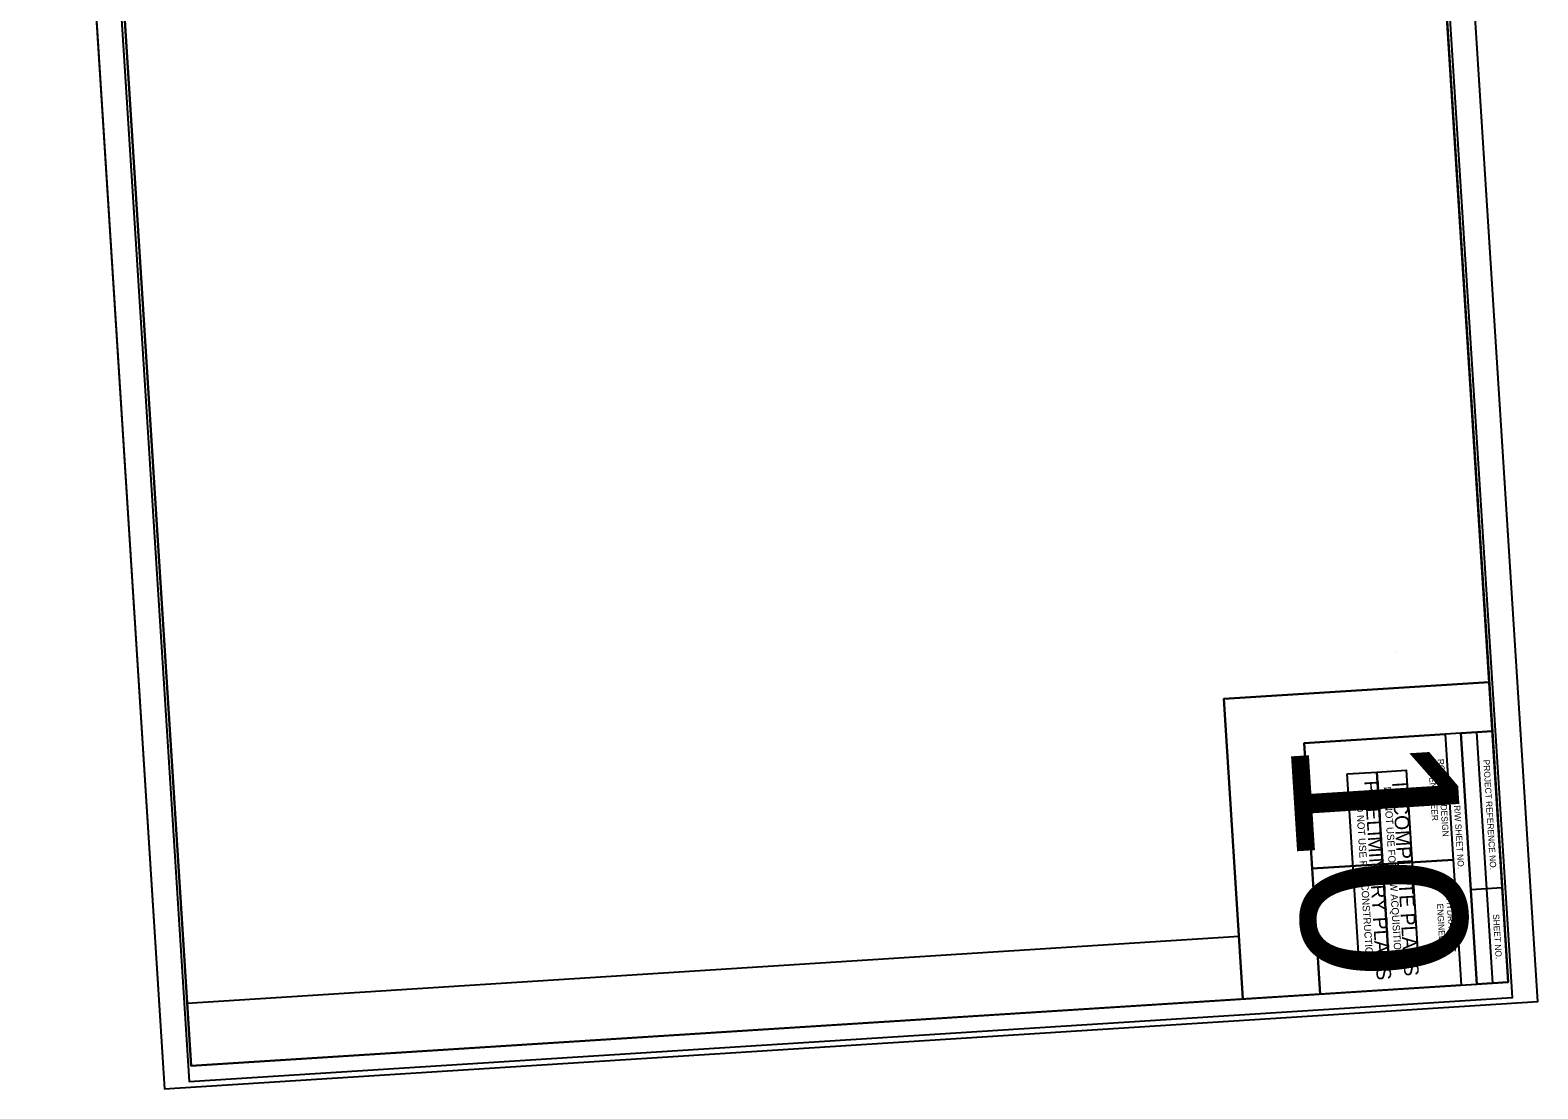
# Model space of a CAD drawing. Extents: x 1778994 to 1784559, y 810461 to 816654.
# Drawn here: x 1780418 to 1781618, y 810461 to 811304 of the extents above; entities that cross this region are included whole.
import ezdxf

# ---------------------------------------------------------------- set-up
doc = ezdxf.new("R2010")
doc.units = 0
for name, color, linetype in [('Sheet Clip Boundary CELL', 7, 'Continuous'), ('Sheet Cutting Line CELL', 7, 'Continuous'), ('Sheet Layout Plan Border', 7, 'Continuous'), ('Sheet North Arrow Point CELL', 7, 'Continuous'), ('Sheet Plan CELL', 7, 'Continuous'), ('Sheet Plan Layout CELL', 7, 'Continuous'), ('Sheet Plot Border Inside CELL', 7, 'Continuous'), ('Sheet Plot Border Outside CELL', 7, 'Continuous'), ('Sheet Sticker Incomplete CELL', 7, 'Continuous'), ('Sheet Sticker Preliminary CELL', 7, 'Continuous')]:
    doc.layers.add(name, color=color, linetype=linetype)

msp = doc.modelspace()

# ---------------------------------------------------------------- linework, layer by layer
at = {"layer": 'Sheet Clip Boundary CELL'}
msp.add_lwpolyline([(1780454.4, 811926.9), (1780543.2, 810529.7), (1781380.1, 810582.9), (1781368.1, 810771.8), (1781579.1, 810785.2), (1781502.3, 811993.5)], close=True, dxfattribs=at)
at = {"layer": 'Sheet Cutting Line CELL'}
for p, q in [((1781617.8, 810530.9), (1781511, 812211)), ((1780418.2, 812141.5), (1780525, 810461.4))]:
    msp.add_line(p, q, dxfattribs=at)
at = {"layer": 'Sheet Layout Plan Border'}
msp.add_lwpolyline([(1780454.4, 811926.9), (1780543.2, 810529.7), (1781380.1, 810582.9), (1781368.1, 810771.8), (1781579.1, 810785.2), (1781502.3, 811993.5)], close=True, dxfattribs=at)
at = {"layer": 'Sheet North Arrow Point CELL'}
msp.add_line((1781504.5, 810809.4), (1781504.5, 810809.4), dxfattribs=at)
at = {"layer": 'Sheet Plan CELL'}
for p, q in [((1781556.6, 810744.5), (1781544.1, 810743.7)), ((1781556.6, 810744.5), (1781569.3, 810544.8)), ((1781556.6, 810744.5), (1781569.3, 810544.8)), ((1781569.1, 810745.3), (1781581.8, 810545.6)), ((1781550.5, 810643.8), (1781438.2, 810636.7)), ((1781589.5, 810621.3), (1781564.5, 810619.7))]:
    msp.add_line(p, q, dxfattribs=at)
for points in [[(1781594.3, 810546.4), (1781499.2, 812043.4), (1780451.3, 811976.8), (1780546.4, 810479.8)], [(1780451.3, 811976.8), (1781499.1, 812043.4), (1781581.6, 810746.1), (1781431.9, 810736.5), (1781444.5, 810536.9), (1780546.4, 810479.8)], [(1781544.1, 810743.7), (1781550.5, 810643.8), (1781438.2, 810636.7), (1781431.9, 810736.5)], [(1781581.6, 810746.1), (1781594.3, 810546.4), (1781569.3, 810544.8), (1781556.6, 810744.5)], [(1781550.5, 810643.8), (1781556.8, 810544), (1781444.5, 810536.9), (1781438.2, 810636.7)]]:
    msp.add_lwpolyline(points, close=True, dxfattribs=at)
at = {"layer": 'Sheet Plan Layout CELL'}
for points in [[(1781499.1, 812043.4), (1780451.3, 811976.8), (1780546.4, 810479.8), (1781383.2, 810533), (1781368.1, 810771.8), (1781579.1, 810785.2)], [(1781368.1, 810771.8), (1781383.2, 810533), (1781594.3, 810546.4), (1781579.1, 810785.2)]]:
    msp.add_lwpolyline(points, close=True, dxfattribs=at)
at = {"layer": 'Sheet Plot Border Inside CELL'}
msp.add_lwpolyline([(1780439, 812129.8), (1780544.7, 810467.2), (1781597.6, 810534.1), (1781491.9, 812196.7)], close=True, dxfattribs=at)
at = {"layer": 'Sheet Plot Border Outside CELL'}
msp.add_lwpolyline([(1780418.2, 812141.5), (1780525, 810461.4), (1781617.8, 810530.9), (1781511, 812211)], close=True, dxfattribs=at)
at = {"layer": 'Sheet Sticker Incomplete CELL'}
msp.add_lwpolyline([(1781489.7, 810713.6), (1781513.1, 810715.1), (1781522.4, 810568.4), (1781499, 810566.9)], close=True, dxfattribs=at)
at = {"layer": 'Sheet Sticker Preliminary CELL'}
msp.add_lwpolyline([(1781466.2, 810712.1), (1781489.7, 810713.6), (1781499, 810566.9), (1781475.5, 810565.4)], close=True, dxfattribs=at)

# ---------------------------------------------------------------- texts
at = {"layer": 'Sheet Plan CELL'}
for s, p in [('ROADWAY DESIGN', (1781538.1, 810723.9)), ('PROJECT REFERENCE NO.', (1781574.3, 810723.3)), ('ENGINEER', (1781531.4, 810709.4)), ('R/W SHEET NO.', (1781551, 810687)), ('ENGINEER', (1781537.4, 810608.7)), ('HYDRAULICS', (1781545.1, 810613)), ('SHEET NO.', (1781582, 810600.4))]:
    msp.add_text(s, height=5, rotation=273.6363, dxfattribs=at).set_placement(p)
at = {"layer": 'Sheet Plan Layout CELL'}
msp.add_text('10', height=131.25, rotation=273.6363, dxfattribs=at).set_placement((1781420.6, 810739.4))
at = {"layer": 'Sheet Sticker Incomplete CELL'}
for s, height, p in [('INCOMPLETE PLANS', 11.52, (1781501.9, 810705.4)), ('DO NOT USE FOR R/W ACQUISITION', 5.76, (1781495.2, 810701.7))]:
    msp.add_text(s, height=height, rotation=273.6363, dxfattribs=at).set_placement(p)
at = {"layer": 'Sheet Sticker Preliminary CELL'}
for s, height, p in [('PRELIMINARY PLANS', 11.52, (1781479.7, 810706.5)), ('DO NOT USE FOR CONSTRUCTION', 5.76, (1781472.9, 810692.9))]:
    msp.add_text(s, height=height, rotation=273.6363, dxfattribs=at).set_placement(p)

doc.saveas('drawing.dxf')
